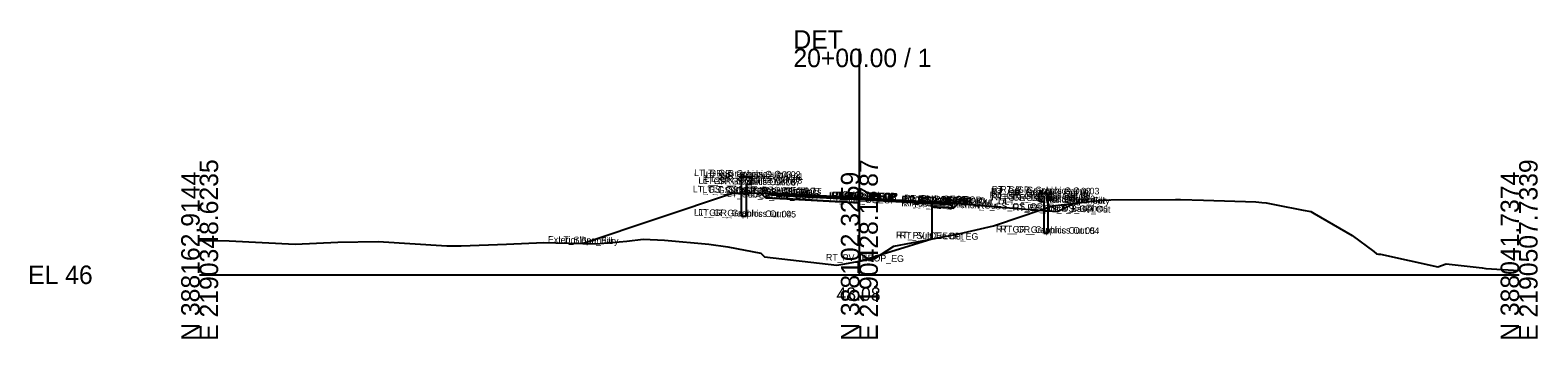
# Model space of a CAD drawing. Extents: x -26 to 1203, y -10 to 9543.
# Drawn here: x 974.3 to 1202.8, y -9.7 to 37 of the extents above; entities that cross this region are included whole.
import ezdxf

# ---------------------------------------------------------------- set-up
doc = ezdxf.new("R2010")
doc.units = 0
for name, color, linetype in [('Default', 7, 'Continuous'), ('Exist CMT Pavement', 7, 'Continuous'), ('Exist Cross Section Cell', 7, 'Continuous'), ('Exist XS Center Line Elevation Label', 7, 'Continuous'), ('Exist XS Ground Line', 7, 'Continuous'), ('Prop CMT Guardrail Graphics', 7, 'Continuous'), ('Prop CMT Pvmt Course 1', 7, 'Continuous'), ('Prop CMT Pvmt Course 1 Wedge', 7, 'Continuous'), ('Prop CMT Pvmt Course 2', 7, 'Continuous'), ('Prop CMT Pvmt Course 2 Wedge', 7, 'Continuous'), ('Prop CMT Pvmt Course 3', 7, 'Continuous'), ('Prop CMT Pvmt Course 3 Wedge', 7, 'Continuous'), ('Prop CMT Pvmt Surface', 7, 'Continuous'), ('Prop CMT Pvmt Surface Shoulder', 7, 'Continuous'), ('Prop CMT Pvmt Wedge Surface 1', 7, 'Continuous'), ('Prop CMT Pvmt Wedge Surface 2', 7, 'Continuous'), ('Prop CMT Pvmt Wedge Surface 3', 7, 'Continuous'), ('Prop CMT Shld Paved Course 1', 7, 'Continuous'), ('Prop CMT Shld Paved Course 2', 7, 'Continuous'), ('Prop CMT Shld Paved Course 3', 7, 'Continuous'), ('Prop CMT Slope Grass', 7, 'Continuous'), ('Prop CMT Subgrade Earthwork', 7, 'Continuous'), ('Scratch_Level_0', 7, 'Continuous')]:
    doc.layers.add(name, color=color, linetype=linetype)

msp = doc.modelspace()

# ---------------------------------------------------------------- linework, layer by layer
at = {"layer": 'Exist CMT Pavement'}
msp.add_lwpolyline([(1100, 2.08), (1111, 5.43)], dxfattribs=at)
at = {"layer": 'Exist Cross Section Cell'}
for p, q in [((1100, 0), (1100, 34.24)), ((1000, 0), (1100, 0)), ((1100, 0), (1200, 0))]:
    msp.add_line(p, q, dxfattribs=at)
at = {"layer": 'Exist XS Ground Line'}
for p, q in [((1124.65, 8.87), (1129.27, 10.45)), ((1129.27, 10.45), (1134.54, 11.07)), ((1134.54, 11.07), (1136.26, 11.26)), ((1136.26, 11.26), (1138.1, 11.33)), ((1138.1, 11.33), (1147.94, 11.41)), ((1147.94, 11.41), (1148.68, 11.41)), ((1148.68, 11.41), (1152.15, 11.3)), ((1152.15, 11.3), (1160.07, 11.03)), ((1160.07, 11.03), (1161.01, 10.96)), ((1161.01, 10.96), (1161.68, 10.91)), ((1161.68, 10.91), (1163.18, 10.6)), ((1163.18, 10.6), (1167.29, 9.79)), ((1167.29, 9.79), (1168.45, 9.56)), ((1168.45, 9.56), (1168.96, 9.27)), ((1168.96, 9.27), (1174.71, 5.96)), ((1115.05, 6.21), (1120.32, 7.41)), ((1120.32, 7.41), (1124.65, 8.87)), ((1000, 5.12), (1001.91, 5.21)), ((1001.91, 5.21), (1004.46, 5.13)), ((1004.46, 5.13), (1014.48, 4.66)), ((1014.48, 4.66), (1020.96, 4.95)), ((1020.96, 4.95), (1027.05, 5.02)), ((1027.05, 5.02), (1037.47, 4.41)), ((1039.62, 4.4), (1046.5, 4.65)), ((1046.5, 4.65), (1052.19, 4.88)), ((1052.19, 4.88), (1053.97, 4.86)), ((1053.97, 4.86), (1060.1, 4.7)), ((1060.1, 4.7), (1064.76, 5.08)), ((1064.76, 5.08), (1067.23, 5.39)), ((1067.23, 5.39), (1070.48, 5.23)), ((1070.48, 5.23), (1077.17, 4.62)), ((1077.17, 4.62), (1080.06, 4.22)), ((1105.2, 4.34), (1110.6, 5.35)), ((1110.6, 5.35), (1115.05, 6.21)), ((1174.71, 5.96), (1177.97, 3.51)), ((1037.47, 4.41), (1039.62, 4.4)), ((1080.06, 4.22), (1085.05, 3.28)), ((1085.05, 3.28), (1085.62, 2.73)), ((1085.62, 2.73), (1096.59, 1.44)), ((1100, 2.08), (1102.34, 2.48)), ((1102.34, 2.48), (1105.2, 4.34)), ((1177.97, 3.51), (1178.38, 3.2)), ((1178.38, 3.2), (1178.69, 3.14)), ((1178.69, 3.14), (1179.01, 3.1)), ((1179.01, 3.1), (1187.66, 1.22)), ((1096.59, 1.44), (1097.5, 1.61)), ((1097.5, 1.61), (1100, 2.08)), ((1187.66, 1.22), (1188.95, 1.67)), ((1188.95, 1.67), (1194.39, 1.05)), ((1194.39, 1.05), (1194.95, 0.93)), ((1194.95, 0.93), (1200, 0.66))]:
    msp.add_line(p, q, dxfattribs=at)
at = {"layer": 'Prop CMT Guardrail Graphics'}
for points in [[(1082.15, 8.82), (1082.15, 14.82)], [(1082.15, 14.82), (1083.49, 14.82), (1083.76, 14.53)], [(1083.76, 13.94), (1083.49, 13.65), (1082.82, 13.65)], [(1083.76, 14.53), (1083.49, 14.24)], [(1083.49, 14.24), (1083.76, 13.94)], [(1082.82, 13.65), (1082.82, 8.82)], [(1128.64, 12.31), (1127.3, 12.31), (1127.03, 12.02)], [(1127.03, 12.02), (1127.3, 11.73)], [(1127.3, 11.73), (1127.03, 11.44)], [(1127.03, 11.44), (1127.3, 11.15), (1127.97, 11.15)], [(1128.64, 6.31), (1128.64, 12.31)], [(1127.97, 11.15), (1127.97, 6.31)], [(1082.82, 8.82), (1082.15, 8.82)], [(1127.97, 6.31), (1128.64, 6.31)]]:
    msp.add_lwpolyline(points, dxfattribs=at)
at = {"layer": 'Prop CMT Pvmt Course 1'}
for points in [[(1100, 11.64), (1089, 12.23)], [(1089, 12.23), (1089, 11.98)], [(1089, 11.98), (1100, 11.39)], [(1100, 11.39), (1100, 11.64)], [(1100, 11.64), (1111, 11.04)], [(1100, 11.39), (1100, 11.64)], [(1111, 10.92), (1100, 11.51)], [(1100, 11.51), (1100, 11.39), (1100, 11.39)], [(1111, 11.04), (1111, 10.79), (1111, 10.79), (1111, 10.92)]]:
    msp.add_lwpolyline(points, dxfattribs=at)
msp.add_lwpolyline([(1100, 11.39), (1100, 11.51), (1100, 11.51), (1100, 11.39)], close=True, dxfattribs=at)
at = {"layer": 'Prop CMT Pvmt Course 1 Wedge'}
msp.add_lwpolyline([(1100, 11.51), (1111, 10.92)], dxfattribs=at)
at = {"layer": 'Prop CMT Pvmt Course 2'}
for points in [[(1089, 11.98), (1100, 11.39)], [(1100, 11.39), (1089, 11.98)], [(1089, 11.98), (1089, 11.98)], [(1100, 11.39), (1100, 11.39)], [(1111, 10.79), (1111, 10.79)]]:
    msp.add_lwpolyline(points, dxfattribs=at)
msp.add_lwpolyline([(1111, 10.79), (1111, 10.79), (1111, 10.79)], close=True, dxfattribs=at)
at = {"layer": 'Prop CMT Pvmt Course 2 Wedge'}
msp.add_lwpolyline([(1100, 11.39), (1111, 10.79)], dxfattribs=at)
at = {"layer": 'Prop CMT Pvmt Course 3'}
for points in [[(1100, 11.39), (1089, 11.98)], [(1089, 11.98), (1089, 11.48)], [(1089, 11.48), (1100, 10.89)], [(1100, 10.89), (1100, 11.39)], [(1111, 10.79), (1111, 10.79), (1111, 10.29), (1111, 10.29)], [(1111, 10.29), (1111, 10.79)]]:
    msp.add_lwpolyline(points, dxfattribs=at)
at = {"layer": 'Prop CMT Pvmt Course 3 Wedge'}
msp.add_lwpolyline([(1100, 11.39), (1111, 10.79)], dxfattribs=at)
at = {"layer": 'Prop CMT Pvmt Surface'}
for points in [[(1100, 11.64), (1089, 12.23)], [(1100, 11.64), (1111, 11.04)]]:
    msp.add_lwpolyline(points, dxfattribs=at)
at = {"layer": 'Prop CMT Pvmt Surface Shoulder'}
for points in [[(1089, 12.23), (1087, 12.34)], [(1111, 11.04), (1113, 10.93)]]:
    msp.add_lwpolyline(points, dxfattribs=at)
at = {"layer": 'Prop CMT Pvmt Wedge Surface 1'}
for points in [[(1100, 11.51), (1111, 10.92)], [(1111, 10.79), (1111, 11.04)], [(1111, 10.92), (1111, 10.79), (1111, 10.79)]]:
    msp.add_lwpolyline(points, dxfattribs=at)
at = {"layer": 'Prop CMT Pvmt Wedge Surface 2'}
for points in [[(1100, 11.39), (1111, 10.79)], [(1111, 10.79), (1111, 11.04)]]:
    msp.add_lwpolyline(points, dxfattribs=at)
at = {"layer": 'Prop CMT Pvmt Wedge Surface 3'}
for points in [[(1100, 11.39), (1111, 10.79)], [(1111, 10.79), (1111, 11.04)]]:
    msp.add_lwpolyline(points, dxfattribs=at)
at = {"layer": 'Prop CMT Shld Paved Course 1'}
for points in [[(1089, 12.23), (1087, 12.34), (1086.76, 12.1)], [(1086.76, 12.1), (1089, 11.98)], [(1089, 11.98), (1089, 12.23)], [(1111, 11.04), (1113, 10.93), (1113.26, 10.67)], [(1111, 10.79), (1111, 11.04)], [(1113.26, 10.67), (1111, 10.79)]]:
    msp.add_lwpolyline(points, dxfattribs=at)
at = {"layer": 'Prop CMT Shld Paved Course 2'}
for points in [[(1089, 11.98), (1086.76, 12.1)], [(1086.76, 12.1), (1086.76, 12.1)], [(1086.76, 12.1), (1089, 11.98)], [(1089, 11.98), (1089, 11.98)], [(1111, 10.79), (1113.26, 10.67)], [(1113.26, 10.67), (1111, 10.79)], [(1111, 10.79), (1111, 10.79)], [(1113.26, 10.67), (1113.26, 10.67)]]:
    msp.add_lwpolyline(points, dxfattribs=at)
at = {"layer": 'Prop CMT Shld Paved Course 3'}
for points in [[(1089, 11.98), (1086.76, 12.1), (1086.26, 12.13), (1085.79, 11.65)], [(1085.79, 11.65), (1089, 11.48)], [(1089, 11.48), (1089, 11.98)], [(1111, 10.79), (1113.26, 10.67), (1113.76, 10.64), (1114.29, 10.11)], [(1111, 10.29), (1111, 10.79)], [(1114.29, 10.11), (1111, 10.29)]]:
    msp.add_lwpolyline(points, dxfattribs=at)
at = {"layer": 'Prop CMT Slope Grass'}
for points in [[(1080.76, 12.3), (1058.12, 4.76)], [(1083.76, 12.32), (1080.76, 12.3)], [(1087, 12.34), (1083.76, 12.32)], [(1113, 10.93), (1127.03, 9.81)], [(1127.03, 9.81), (1130.03, 9.57)], [(1130.03, 9.57), (1130.04, 9.57), (1132.58, 10.84)], [(1130.03, 9.57), (1132.58, 10.84)]]:
    msp.add_lwpolyline(points, dxfattribs=at)
at = {"layer": 'Prop CMT Subgrade Earthwork'}
for points in [[(1085.79, 11.65), (1085.12, 12.33)], [(1089, 11.48), (1085.79, 11.65)], [(1100, 10.89), (1089, 11.48)], [(1111, 10.29), (1111, 10.29)], [(1111, 10.29), (1111, 5.43)], [(1111, 10.29), (1114.29, 10.11)], [(1114.29, 10.11), (1114.96, 10.78)]]:
    msp.add_lwpolyline(points, dxfattribs=at)

# ---------------------------------------------------------------- texts
at = {"layer": 'Default'}
msp.add_text('-', height=0.0001, dxfattribs=at).set_placement((1000, 0))
at = {"layer": 'Exist Cross Section Cell'}
for s, p in [('DET', (1090, 34.24)), ('20+00.00 / 1', (1090, 31.44)), ('EL 46', (974, -1.4))]:
    msp.add_text(s, height=2.8, dxfattribs=at).set_placement(p)
for s, p in [('E 2190348.6235', (1002.8, -10)), ('E 2190428.1787', (1102.8, -10)), ('E 2190507.7339', (1202.8, -10)), ('N 388162.9144', (1000, -10)), ('N 388102.3259', (1100, -10)), ('N 388041.7374', (1200, -10))]:
    msp.add_text(s, height=2.8, rotation=90, dxfattribs=at).set_placement(p)
at = {"layer": 'Exist XS Center Line Elevation Label'}
msp.add_text('48.08', height=2, dxfattribs=at).set_placement((1096.52, -3.92))
at = {"layer": 'Scratch_Level_0'}
for s, p in [('LT_GR_Graphics Out 03', (1074.94, 14.96)), ('LT_GR_Graphics Out 06', (1075.59, 13.79)), ('LT_GR_Graphics Out 07', (1076.25, 13.79)), ('LT_GR_Graphics Out 09', (1076.26, 14.38)), ('LT_GR_Graphics Out 02', (1076.29, 14.96)), ('LT_GR_Graphics Out 08', (1076.53, 14.08)), ('LT_GR_Graphics Out 01', (1076.7, 14.66)), ('LT_GS_OS_GR_Face_Graphics', (1074.75, 12.49)), ('LT_GS_OS_CTL', (1076.22, 12.39)), ('LT_Sub_Trench_Out_DLT', (1077.77, 12.47)), ('LT_Sub_Trench_Out', (1079.9, 11.77)), ('LT_PS3_Shelf_Out', (1080.92, 12.23)), ('LT_PS3_OEOP', (1082.55, 12.18)), ('LT_PS2_OEOP', (1082.55, 12.18)), ('LT_PS1_OEOP', (1082.91, 12.42)), ('LT_PV2_OEOT', (1084.75, 12.06)), ('LT_PV3_OEOT', (1084.75, 12.06)), ('LT_Sub_OEOT', (1084.77, 11.56)), ('LT_PV1_OEOT', (1084.87, 12.31)), ('LT_PV2_OEEOP', (1095.39, 11.48)), ('LT_PV3_OEEOP', (1095.39, 11.48)), ('LT_Sub_OEEOP', (1095.42, 10.98)), ('LT_PV1_OEEOP', (1095.51, 11.6)), ('RT_PV2_IEEOP', (1095.71, 11.47)), ('RT_PV3_IEEOP', (1095.71, 11.47)), ('LT_PV2_IEEOP', (1095.77, 11.47)), ('RT_PV1_IEEOP', (1095.83, 11.59)), ('LT_PV1_IEEOP', (1095.89, 11.59)), ('PV2_PGL', (1097.35, 11.44)), ('PV1_PGL', (1097.47, 11.69)), ('RT_PV2_OEEOP', (1106.33, 10.88)), ('RT_PV3_OEEOP', (1106.33, 10.88)), ('RT_PV1_OEEOP', (1106.45, 11.01)), ('RT_PV3_OEOT', (1106.69, 10.88)), ('RT_PV2_OEOT', (1106.69, 10.88)), ('RT_PV1_OEOT', (1106.81, 11.12)), ('RT_Sub_Trench_Out_DLT', (1107.55, 10.92)), ('RT_PS3_Shelf_Out', (1108.36, 10.75)), ('RT_PS1_OEOP', (1108.85, 11.02)), ('RT_PS3_OEOP', (1108.99, 10.75)), ('RT_PS2_OEOP', (1108.99, 10.75)), ('RT_GR_Graphics Out 08', (1119.74, 11.58)), ('RT_GR_Graphics Out 01', (1119.92, 12.16)), ('RT_GR_Graphics Out 07', (1120, 11.29)), ('RT_GR_Graphics Out 09', (1120.02, 11.87)), ('RT_GR_Graphics Out 02', (1120.05, 12.45)), ('RT_GR_Graphics Out 06', (1120.68, 11.29)), ('RT_GR_Graphics Out 03', (1121.36, 12.45)), ('Exterior Boundary', (1127.24, 10.94)), ('RT_Slope_Cut', (1128.52, 10.92)), ('RT_Slope_Fill', (1128.76, 10.91)), ('LT_GR_Graphics Out 04', (1074.92, 8.96)), ('LT_GR_Graphics Out 05', (1075.6, 8.96)), ('RT_Sub_OEEOP', (1106.36, 10.38)), ('RT_Sub_OEOT', (1106.71, 10.38)), ('RT_Sub_Trench_Out', (1108.34, 10.23)), ('RT_GS_OS_GR_Face_Graphics', (1117.97, 9.99)), ('RT_SS_Ditch_Base_Out', (1123.24, 9.7)), ('RT_GS_OS_CTL', (1125.44, 9.66)), ('RT_GR_Graphics Out 05', (1120.69, 6.45)), ('RT_GR_Graphics Out 04', (1121.35, 6.45)), ('Exterior Boundary', (1052.78, 4.86)), ('LT_Slope_Fill', (1054.36, 4.83)), ('RT_PV_OEEOP_EG', (1105.54, 5.54)), ('RT_Sub Tie Out', (1106.1, 5.52)), ('RT_PV_IEEOP_EG', (1094.92, 2.17))]:
    msp.add_text(s, height=1, rotation=358.8836, dxfattribs=at).set_placement(p)

doc.saveas('drawing.dxf')
